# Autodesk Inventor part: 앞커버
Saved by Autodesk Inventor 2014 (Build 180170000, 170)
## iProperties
Created: 2026-03
Part Number: 앞커버
Material: 강철, 연강
Document SubType Name: Modeling
Designer: dg
Density: 7.86 g/cm^3
Appearance: 강철
Mass: 157.29 g
Surface Area: 83.5374 cm^2
Volume: 20.0114 cm^3
Author: jhkim
Creation Date: 2025-06-27
Sending System: Autodesk Inventor 2026
Preprocessor: ST-DEVELOPER v20.1
Author: dg
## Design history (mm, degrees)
node "앞커버1"
node "솔리드1"
node "기준1"
